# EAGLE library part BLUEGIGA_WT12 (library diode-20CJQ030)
BlueGiga's WT12 Bluetooth Module (2.0+EDR) Description: BlueCore4 is a single chip Bluetooth solution which implements the Bluetooth radio transceiver and also an on chip microcontroller. BlueCore4 implements Bluetooth® 2.0+EDR (Enhanced Data Rate) and it can deliver data rates up to 3 Mbps. The microcontroller (MCU) on BlueCore04 acts as interrupt controller and event timer run the Bluetooth software stack and control the radio and host interfaces. A 16-bit reduced instruction set computer (RISC) microcontroller is used for low power consumption and efficient use of memory. BlueCore04 has 48Kbytes of on-chip RAM is provided to support the RISC MCU and is shared between the ring buffers used to hold voice/data for each active connection and the general purpose memory required by the Bluetooth stack. Featrures: Fully Qualified Bluetooth system v2.0 + EDR, CE and FCC Integrated chip antenna Industrial temperature range from -40oC to +85oC Enhanced Data Rate (EDR) compliant with v2.0.E.2 of specification for both 2Mbps and 3Mbps modulation modes RoHS Compliant Full Speed Bluetooth Operation with Full Piconet Scatternet Support USB version 1.2 UART with bypass mode Support for 802.11 Coexistence 8Mbits of External Flash Applications: Hand held terminals Industrial devices Point-of-Sale systems PCs Personal Digital Assistants (PDAs) Computer Accessories Access Points Please send any comments to: messi@users.sourceforge.net
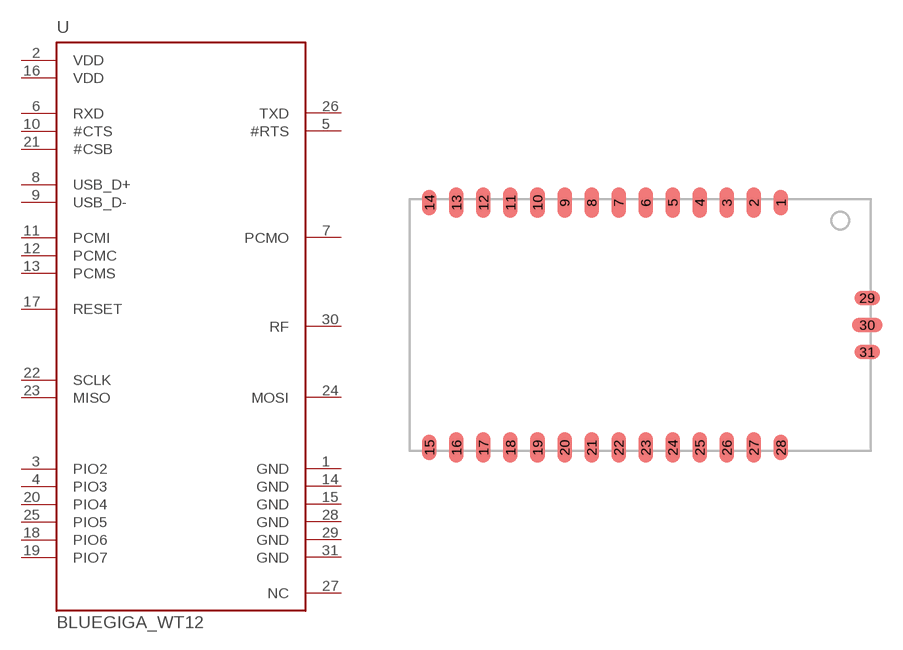
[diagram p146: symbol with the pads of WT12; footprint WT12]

Designator prefix U

## BLUEGIGA_WT12W  [WT12]
1  GND  pwr
2  VDD  pwr
3  PIO2
4  PIO3
5  #RTS  out
6  RXD  in
7  PCMO  out
8  USB_D+  sup
9  USB_D-  sup
10  #CTS  in
11  PCMI  in
12  PCMC
13  PCMS
14  GND  pwr
15  GND  pwr
16  VDD  pwr
17  RESET  in
18  PIO6
19  PIO7
20  PIO4
21  #CSB  in
22  SCLK
23  MISO  in
24  MOSI  out
25  PIO5
26  TXD  out
27  NC  nc
28  GND  pwr
29  GND  pwr
30  RF  pas
31  GND  pwr

## Footprint WT12 (pad centres in mm)
Footprint for the WT12 Bluetooth module from BlueGiga
smd 0.8 x 1.4: 1 7.8,6.8; 14 -11.7,6.8; 15 -11.7,-6.8; 28 7.8,-6.8
smd 0.8 x 1.7: 2 6.3,6.8; 3 4.8,6.8; 4 3.3,6.8; 5 1.8,6.8; 6 0.3,6.8; 7 -1.2,6.8; 8 -2.7,6.8; 9 -4.2,6.8; 10 -5.7,6.8; 11 -7.2,6.8; 12 -8.7,6.8; 13 -10.2,6.8; 16 -10.2,-6.8; 17 -8.7,-6.8; 18 -7.2,-6.8; 19 -5.7,-6.8; 20 -4.2,-6.8; 21 -2.7,-6.8; 22 -1.2,-6.8; 23 0.3,-6.8; 24 1.8,-6.8; 25 3.3,-6.8; 26 4.8,-6.8; 27 6.3,-6.8
smd 1.4 x 0.8: 29 12.6,1.5; 31 12.6,-1.5
smd 1.7 x 0.8: 30 12.6,0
